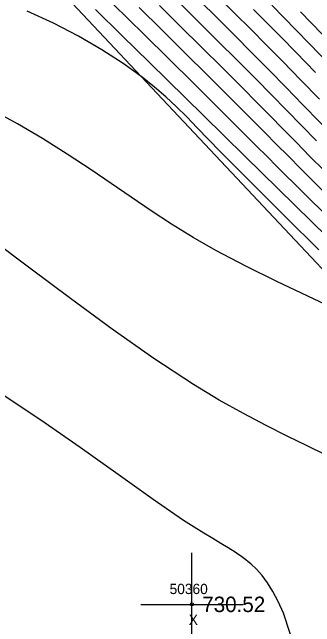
# Model space of a CAD drawing. Extents: x 1378535 to 1380697, y 997729 to 1000024.
# Drawn here: x 1379507.2 to 1379536.7, y 999000.3 to 999060.1 of the extents above; entities that cross this region are included whole.
import ezdxf

# ---------------------------------------------------------------- set-up
doc = ezdxf.new("R2010")
doc.units = 0
for name, color, linetype in [('RD_DTM_BkLn2', 7, 'Continuous'), ('RD_DTM_Major1', 7, 'Continuous'), ('RD_DTM_Minor1', 7, 'Continuous'), ('RD_EX_Misc', 7, 'Continuous'), ('RD_EX_Misc_txCode', 7, 'Continuous'), ('RD_EX_TX_Misc_ELEV', 7, 'Continuous'), ('RD_SMD_Locator', 7, 'Continuous')]:
    doc.layers.add(name, color=color, linetype=linetype)

msp = doc.modelspace()

# ---------------------------------------------------------------- linework, layer by layer
at = {"layer": 'RD_DTM_BkLn2'}
msp.add_lwpolyline([(1379546.679, 999025.297), (1379508.429, 999065.934), (1379476.253, 999096.185), (1379454.22, 999110.396), (1379428.749, 999089.976)], dxfattribs=at)
at = {"layer": 'RD_DTM_Major1'}
for points in [[(1379552.566, 999033.796), (1379551.072, 999035.312), (1379549.431, 999036.967), (1379547.69, 999038.719), (1379545.882, 999040.541), (1379544.037, 999042.406), (1379542.188, 999044.285), (1379540.511, 999046.002), (1379538.852, 999047.709), (1379537.206, 999049.406), (1379535.566, 999051.093), (1379533.928, 999052.77), (1379532.286, 999054.438), (1379530.585, 999056.15), (1379528.884, 999057.849), (1379527.193, 999059.531), (1379525.522, 999061.194)], [(1379539.347, 999036.827), (1379536.383, 999039.738), (1379529.902, 999046.083), (1379525.872, 999050.034), (1379520.603, 999055.187), (1379517.922, 999057.815), (1379515.362, 999060.337)]]:
    msp.add_lwpolyline(points, dxfattribs=at)
at = {"layer": 'RD_DTM_Minor1'}
for points in [[(1379540.893, 999037.324), (1379535.531, 999042.607), (1379533.059, 999045.051), (1379532.036, 999046.067), (1379531.051, 999047.048), (1379530.086, 999048.01), (1379528.155, 999049.937), (1379527.155, 999050.933), (1379524.883, 999053.185), (1379522.494, 999055.545), (1379520.076, 999057.927), (1379515.51, 999062.422)], [(1379537.176, 999051.626), (1379535.364, 999053.49), (1379533.579, 999055.313), (1379532.019, 999056.89), (1379530.484, 999058.43), (1379528.97, 999059.943), (1379527.475, 999061.439)], [(1379537.619, 999044.683), (1379536.249, 999046.064), (1379534.927, 999047.405), (1379533.631, 999048.721), (1379532.342, 999050.03), (1379531.038, 999051.35), (1379529.697, 999052.699), (1379527.718, 999054.675), (1379525.674, 999056.702), (1379523.613, 999058.738), (1379521.586, 999060.743)], [(1379536.883, 999047.564), (1379535.416, 999049.066), (1379533.956, 999050.559), (1379532.487, 999052.056), (1379530.993, 999053.566), (1379529.153, 999055.41), (1379527.282, 999057.271), (1379525.408, 999059.128), (1379523.559, 999060.961)], [(1379538.242, 999054.919), (1379536.175, 999057.052), (1379534.91, 999058.345), (1379533.697, 999059.58), (1379532.518, 999060.777)], [(1379537.105, 999036.976), (1379533.881, 999040.161), (1379530.862, 999043.158), (1379528.216, 999045.818), (1379527.885, 999046.155), (1379527.563, 999046.484), (1379527.25, 999046.804), (1379526.65, 999047.421), (1379526.361, 999047.719), (1379525.271, 999048.846), (1379524.241, 999049.896), (1379523.23, 999050.892), (1379522.194, 999051.855), (1379521.093, 999052.805), (1379519.884, 999053.764), (1379518.044, 999055.086), (1379515.971, 999056.426), (1379513.699, 999057.748), (1379511.265, 999059.016), (1379508.702, 999060.193)], [(1379537.644, 999042.576), (1379535.342, 999044.866), (1379534.139, 999046.07), (1379532.982, 999047.233), (1379531.852, 999048.372), (1379530.725, 999049.506), (1379529.583, 999050.654), (1379528.403, 999051.835), (1379526.278, 999053.949), (1379524.056, 999056.148), (1379521.808, 999058.366), (1379519.607, 999060.538)], [(1379536.8, 999054.209), (1379534.874, 999056.185), (1379533.459, 999057.623), (1379532.087, 999059.008), (1379530.744, 999060.36)], [(1379537.48, 999057.911), (1379536.373, 999059.054), (1379535.317, 999060.14)], [(1379538.879, 999031.117), (1379536.031, 999032.478), (1379533.024, 999033.903), (1379529.992, 999035.384), (1379527.069, 999036.913), (1379524.855, 999038.183), (1379522.765, 999039.474), (1379520.765, 999040.78), (1379518.817, 999042.098), (1379516.886, 999043.42), (1379514.936, 999044.743), (1379512.585, 999046.286), (1379510.178, 999047.791), (1379507.735, 999049.227), (1379505.277, 999050.563)], [(1379537.752, 999017.021), (1379535.964, 999017.909), (1379534.038, 999018.853), (1379531.97, 999019.887), (1379529.758, 999021.044), (1379527.398, 999022.36), (1379524.889, 999023.868), (1379521.019, 999026.409), (1379516.976, 999029.256), (1379512.903, 999032.24), (1379508.946, 999035.195), (1379505.247, 999037.954)], [(1379535.011, 998997.572), (1379533.653, 999001.609), (1379533.147, 999002.756), (1379532.632, 999003.737), (1379532.109, 999004.573), (1379531.574, 999005.286), (1379531.029, 999005.896), (1379530.471, 999006.424), (1379530.231, 999006.627), (1379529.988, 999006.822), (1379529.74, 999007.009), (1379529.487, 999007.191), (1379529.227, 999007.369), (1379528.961, 999007.545), (1379528.289, 999007.968), (1379527.562, 999008.406), (1379526.771, 999008.876), (1379525.906, 999009.395), (1379524.96, 999009.979), (1379523.923, 999010.644), (1379520.955, 999012.674), (1379517.542, 999015.109), (1379513.846, 999017.754), (1379510.033, 999020.412), (1379506.265, 999022.891)]]:
    msp.add_lwpolyline(points, dxfattribs=at)
at = {"layer": 'RD_EX_Misc'}
for p, q in [((1379524.751, 998997.479), (1379524.751, 999007.479)), ((1379519.751, 999002.479), (1379529.751, 999002.479))]:
    msp.add_line(p, q, dxfattribs=at)
at = {"layer": 'RD_SMD_Locator'}
msp.add_circle((1379524.751, 999002.479), 0.15, dxfattribs=at)

# ---------------------------------------------------------------- texts
at = {"layer": 'RD_EX_Misc_txCode'}
for s, p in [('50360', (1379522.57, 999003.479)), ('X', (1379524.436, 999000.479))]:
    msp.add_text(s, height=1, dxfattribs=at).set_placement(p)
at = {"layer": 'RD_EX_TX_Misc_ELEV'}
msp.add_text('730.52', height=1.5, dxfattribs=at).set_placement((1379525.751, 999001.729))

doc.saveas('drawing.dxf')
